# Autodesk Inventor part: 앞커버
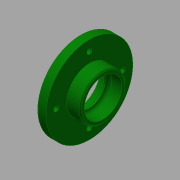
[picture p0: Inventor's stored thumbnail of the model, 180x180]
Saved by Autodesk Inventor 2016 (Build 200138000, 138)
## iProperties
Created: 2015-09
Part Number: 앞커버
Material: 알루미늄 6061
Document SubType Name: Modeling
Designer: mduedu
Density: 2.71 g/cm^3
Mass: 58.9874 g
Surface Area: 98.7754 cm^2
Volume: 21.7666 cm^3
Appearance: 진녹색
Author: mduedu
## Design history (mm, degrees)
sketch "스케치1"
  geometry: L1 (-4, 67)-(-16, 67); L2 (-16, 67)-(-16, 85); L3 (-16, 85)-(-24, 85); L4 (-24, 85)-(-24, 70.5); L5 (-27, 70.5)-(-27, 61); L6 (-27, 61)-(-4, 61); L7 (-4, 61)-(-4, 67); L8 (-79.5, 39.5)-(-79.5, 54.5) reference; L9 (48.5, 54.5)-(48.5, 39.5) reference; L10 (-79.5, 47)-(48.5, 47); L11 (-24, 70.5)-(-27, 70.5); 3 further points
  constraints: 18 end point, 6 parallel, 4 midpoint, 1 horizontal, 1 perpendicular, 1 vertical alignment
  dimensions: "d0" = 23 distance between parallel lines of L7 L5; "d2" = 28 diameter of L6 L10; "d3" = 40 diameter of L1 L10; "d5" = 12 distance of L1.start L1.end; "d6" = 76 diameter of L3 L10; "d7" = 8 distance of L2.end L3.end; "d8" = 47 diameter of L4.end L10
revolve "회전1" sketch "스케치1" stored, may be unused: angle "d4" = 90 deg
sketch "스케치2"
  geometry: C1 r 38 at (0, 0) reference; 2 further points
  constraints: 1 coincident
hole "구멍1" sketch "스케치2" at (0, 0) diameter "d11" = 33; stored, may be unused: countersink angle "d15" = 90 deg, drill point angle "d17" = 0 deg; dims "d12" = 6, "d13" = 4, "d14" = 2, "d16" = 12
fillet "모깎기1" dims "d18" = 3
fillet "모깎기2" dims "d19" = 1
sketch "스케치3"
  geometry: C1 r 38 at (0, 0) reference; 2 further points
  constraints: 1 coincident
hole "구멍2" sketch "스케치3" at (0, 0) diameter "d20" = 40; stored, may be unused: countersink angle "d24" = 90 deg, drill point angle "d26" = 0 deg; dims "d21" = 6, "d22" = 4, "d23" = 2, "d25" = 8.4
fillet "모깎기3" dims "d27" = 0.4
chamfer "모따기1" distance "d28" = 0.8; stored, may be unused: second distance "d29" = 2, angle "d30" = 30 deg
chamfer "모따기2" distance "d61" = 1; stored, may be unused: second distance "d62" = 2, angle "d63" = 45 deg
sketch "스케치7" dims "d56" = 58
  geometry: C1 r 38 at (0, 0) reference; 5 further points
  constraints: 2 vertical alignment, 1 coincident, 7 other
  dimensions: "d59" = 360 deg dimension on C1.centre point (0, 29) (derived)
sketch "스케치8"
  geometry: 4 further points
  constraints: 4 other
hole "구멍5" sketch "스케치8" at (-29, 0), (0, -29), (29, 0), (0, 29) diameter "d64" = 4.5; stored, may be unused: countersink angle "d68" = 90 deg, drill point angle "d70" = 0 deg; dims "d65" = 6, "d66" = 8, "d67" = 4.6, "d69" = 8
chamfer "모따기3" distance "d71" = 1; stored, may be unused: second distance "d72" = 2, angle "d73" = 45 deg
node "솔리드1"
node "참조1"
node "참조2"
